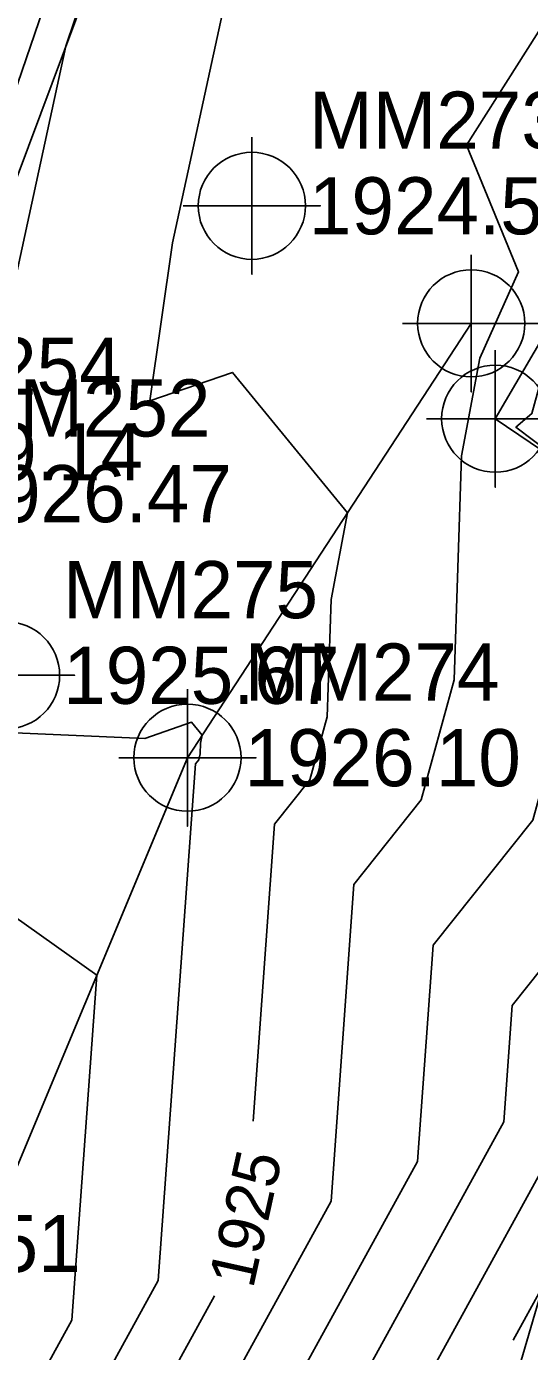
# Model space of a CAD drawing. Extents: x 1004378 to 1005103, y 553854 to 554288.
# Drawn here: x 1004979.8 to 1005001.8, y 554194.9 to 554252.9 of the extents above; entities that cross this region are included whole.
import ezdxf

# ---------------------------------------------------------------- set-up
doc = ezdxf.new("R2010")
doc.units = 0
for name, color, linetype in [('DTM Contours Major', 7, 'Continuous'), ('DTM Contours Major Text', 7, 'Continuous'), ('DTM Contours Minor', 7, 'Continuous'), ('Exist DTM Breakline', 7, 'Continuous'), ('Exist DTM Breakline Cogo Comment', 7, 'Continuous'), ('Exist DTM Breakline Cogo Elevation', 7, 'Continuous'), ('Exist DTM Breakline Cogo Number', 7, 'Continuous'), ('Exist DTM Breakline Cogo Point CELL', 7, 'Continuous'), ('Exist DTM Regular Point CELL', 7, 'Continuous'), ('Exist DTM Regular Point Cogo Elevation', 7, 'Continuous'), ('Exist DTM Regular Point Cogo Number', 7, 'Continuous'), ('Exist Roads EOP', 7, 'Continuous')]:
    doc.layers.add(name, color=color, linetype=linetype)

msp = doc.modelspace()

# ---------------------------------------------------------------- linework, layer by layer
at = {"layer": 'DTM Contours Major'}
for points in [[(1005018.059, 554271.971), (1005001.339, 554273.303), (1004997.708, 554270.886), (1004993.064, 554264.498), (1004995.16, 554263.287), (1004993.526, 554262.254), (1004988.609, 554254.469), (1004986.224, 554243.456), (1004985.222, 554236.535), (1004988.837, 554237.778), (1004993.872, 554231.637), (1004993.15, 554227.832), (1004992.988, 554222.697), (1004992.231, 554219.939), (1004990.684, 554217.999), (1004989.751, 554205.001)], [(1005085.253, 554232.251), (1005065.7, 554222.397), (1005064.933, 554221.918), (1005064.991, 554222.066), (1005065.344, 554223.049), (1005065.952, 554224.718), (1005066.048, 554225.004), (1005062.678, 554224.698), (1005047.268, 554222.206), (1005031.925, 554218.126), (1005030.77, 554217.777), (1005026.361, 554215.994), (1005026.142, 554215.905), (1005025.965, 554215.797), (1005018.761, 554211.473), (1005015.099, 554208.571), (1005013.055, 554206.965), (1005008.097, 554202.389), (1005006.285, 554199.827), (1005002.41, 554197.77), (1005001.113, 554195.406)], [(1004988.055, 554197.353), (1004983.519, 554189.087), (1004981.07, 554183.147), (1004980.472, 554180.378), (1004981.231, 554169.159), (1004982.126, 554161.833), (1004982.368, 554159.624), (1004982.603, 554156.477), (1004979.182, 554142.834), (1004980.705, 554127.374), (1004976.99, 554114.65), (1004972.242, 554102.28), (1004972.017, 554101.096)]]:
    msp.add_lwpolyline(points, dxfattribs=at)
at = {"layer": 'DTM Contours Minor'}
for points in [[(1004979.178, 554270.892), (1004979.965, 554270.572), (1004983.011, 554268.448), (1004986.513, 554266.767), (1004981.55, 554252.068), (1004978.949, 554240.061)], [(1004976.979, 554268.984), (1004983.286, 554266.522), (1004984.471, 554265.976), (1004984.714, 554265.859), (1004984.509, 554265.252), (1004975.486, 554238.886)], [(1005049.674, 554261.493), (1005048.336, 554262.162), (1005048.391, 554261.154), (1005047.971, 554261.002), (1005047.219, 554261.151), (1005038.078, 554260.42), (1005037.81, 554261.029), (1005038.533, 554264.244), (1005038.474, 554264.547), (1005022.134, 554266.393), (1005018.739, 554266.663), (1005008.512, 554259.857), (1005006.97, 554257.736), (1005007.666, 554257.334), (1005003.478, 554254.686), (1004999.082, 554247.727), (1005001.345, 554242.184), (1004999.666, 554238.402), (1004998.854, 554234.12), (1004998.544, 554224.321), (1004997.101, 554219.058), (1004994.148, 554215.354), (1004993.153, 554201.493), (1004985.717, 554187.945)], [(1005045.835, 554249.855), (1005031.335, 554247.323), (1005028.865, 554247.126), (1005028.25, 554248.522), (1005028.121, 554248.671), (1005027.728, 554248.629), (1005025.559, 554248.116), (1005024.184, 554248.111), (1005015.878, 554249.159), (1005015.053, 554249.514), (1005014.698, 554249.961), (1005009.806, 554249.475), (1005009.131, 554249.89), (1005002.516, 554238.096), (1005001.94, 554235.973), (1005001.24, 554235.376), (1005004.325, 554233.049), (1005004.1, 554225.944), (1005001.971, 554218.176), (1004997.612, 554212.709), (1004996.931, 554203.23), (1004987.915, 554186.802)], [(1005081.907, 554236.456), (1005081.575, 554236.342), (1005069.531, 554230.299), (1005070.085, 554231.824), (1005070.64, 554233.472), (1005054.504, 554232.01), (1005052.782, 554231.968), (1005051.198, 554231.714), (1005032.836, 554227.453), (1005025.92, 554225.538), (1005021.623, 554223.448), (1005019.859, 554222.732), (1005013.96, 554219.101), (1005012.402, 554218.937), (1005011.71, 554216.413), (1005004.54, 554207.42), (1005004.489, 554206.704), (1004992.311, 554184.516)], [(1004977.31, 554222.084), (1004985.01, 554221.756), (1004987.05, 554222.458), (1004987.512, 554221.894), (1004987.446, 554221.545), (1004987.431, 554221.074), (1004987.362, 554220.821), (1004987.22, 554220.643), (1004985.596, 554198.019), (1004981.321, 554190.23), (1004979.533, 554185.894)], [(1005006.84, 554217.294), (1005001.076, 554210.065), (1005000.71, 554204.967), (1004990.113, 554185.659)], [(1004978.6, 554214.438), (1004982.901, 554211.383), (1004981.817, 554196.282), (1004979.123, 554191.373)]]:
    msp.add_lwpolyline(points, dxfattribs=at)
at = {"layer": 'Exist DTM Breakline'}
for points in [[(1004977.38, 554270.285), (1004987.161, 554267.094), (1004974.231, 554232.47), (1004965.01, 554203.394)], [(1005011.587, 554228.131), (1005018.939, 554243.236), (1005014.748, 554247.317), (1005015.189, 554250.493), (1005008.958, 554250.519), (1005000.334, 554235.751), (1005011.587, 554228.131)], [(1004999.282, 554239.926), (1004986.87, 554220.91), (1004973.315, 554188.37), (1004969.818, 554151.968), (1004967.766, 554123.144), (1004953.718, 554097.079)], [(1004987.71, 553883.194), (1004993.763, 553908.865), (1004995.956, 553952.192), (1004996.06, 553992.449), (1004993.928, 554035.876), (1004994.309, 554070.389), (1004993.033, 554080.737), (1004990.275, 554106.198), (1004991.435, 554130.882), (1004994.664, 554165.005), (1004997.714, 554181.706), (1005005.106, 554206.988)]]:
    msp.add_lwpolyline(points, dxfattribs=at)
at = {"layer": 'Exist DTM Breakline Cogo Point CELL'}
for points in [[(1004999.282, 554242.926), (1004999.282, 554236.926), (1004999.282, 554239.926), (1005002.282, 554239.926), (1004996.282, 554239.926)], [(1005000.334, 554238.751), (1005000.334, 554232.751), (1005000.334, 554235.751), (1005003.334, 554235.751), (1004997.334, 554235.751)], [(1004986.87, 554223.91), (1004986.87, 554217.91), (1004986.87, 554220.91), (1004989.87, 554220.91), (1004983.87, 554220.91)]]:
    msp.add_lwpolyline(points, dxfattribs=at)
for centre in [(1004999.282, 554239.926), (1005000.334, 554235.751), (1004986.87, 554220.91)]:
    msp.add_circle(centre, 2.344, dxfattribs=at)
at = {"layer": 'Exist DTM Regular Point CELL'}
for points in [[(1004989.687, 554248.072), (1004989.687, 554242.072), (1004989.687, 554245.072), (1004992.687, 554245.072), (1004986.687, 554245.072)], [(1004978.936, 554227.517), (1004978.936, 554221.517), (1004978.936, 554224.517), (1004981.936, 554224.517), (1004975.936, 554224.517)]]:
    msp.add_lwpolyline(points, dxfattribs=at)
for centre in [(1004989.687, 554245.072), (1004978.936, 554224.517)]:
    msp.add_circle(centre, 2.344, dxfattribs=at)
at = {"layer": 'Exist Roads EOP'}
msp.add_spline([(1005026.381, 554243.671), (1005017.049, 554225.785), (1005004.478, 554185.698), (1005001.445, 554147.868), (1005001.025, 554103.612), (1005002.785, 554054.517)], degree=3, dxfattribs=at)

# ---------------------------------------------------------------- texts
at = {"layer": 'DTM Contours Major Text'}
msp.add_text('1925', height=2, rotation=77.50102, dxfattribs=at).set_placement((1004989.737, 554197.62))
at = {"layer": 'Exist DTM Breakline Cogo Comment'}
msp.add_text('EL*40051', height=2.5, dxfattribs=at).set_placement((1004967.51, 554198.394))
at = {"layer": 'Exist DTM Breakline Cogo Elevation'}
for s, p in [('1929.14', (1004972.843, 554233.047)), ('1926.47', (1004976.731, 554231.22)), ('1926.10', (1004989.37, 554219.66))]:
    msp.add_text(s, height=2.5, dxfattribs=at).set_placement(p)
at = {"layer": 'Exist DTM Breakline Cogo Number'}
for s, p in [('MM254', (1004972.843, 554236.797)), ('MM252', (1004976.731, 554234.97)), ('MM274', (1004989.37, 554223.41))]:
    msp.add_text(s, height=2.5, dxfattribs=at).set_placement(p)
at = {"layer": 'Exist DTM Regular Point Cogo Elevation'}
for s, p in [('1924.52', (1004992.187, 554243.822)), ('1925.67', (1004981.436, 554223.267))]:
    msp.add_text(s, height=2.5, dxfattribs=at).set_placement(p)
at = {"layer": 'Exist DTM Regular Point Cogo Number'}
for s, p in [('MM273', (1004992.187, 554247.572)), ('MM275', (1004981.436, 554227.017))]:
    msp.add_text(s, height=2.5, dxfattribs=at).set_placement(p)

doc.saveas('drawing.dxf')
